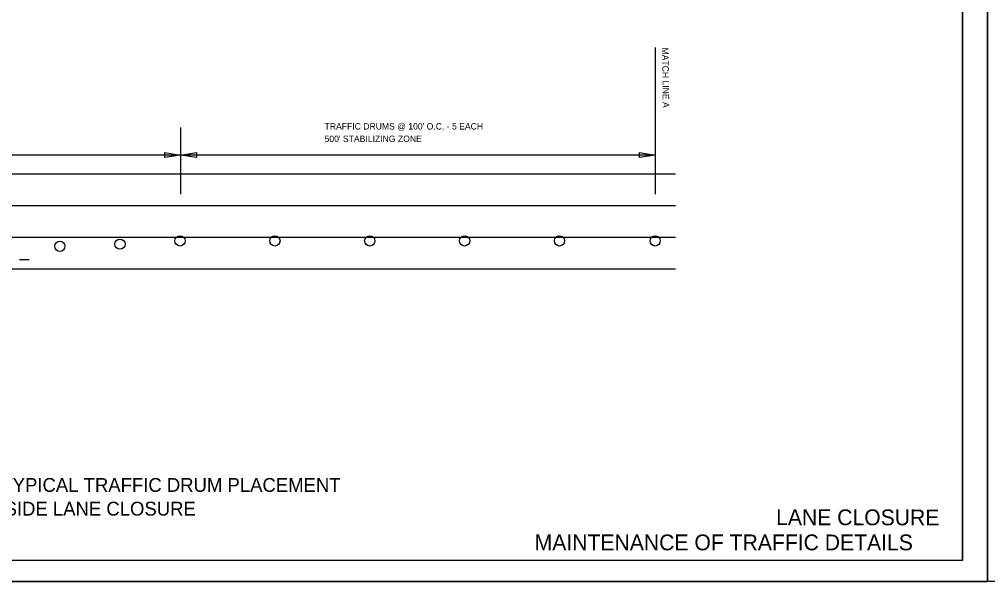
# Model space of a CAD drawing. Extents: x 1397271 to 1411271, y 376395 to 377888.
# Drawn here: x 1402985 to 1404271, y 376395 to 377141 of the extents above; entities that cross this region are included whole.
import ezdxf

# ---------------------------------------------------------------- set-up
doc = ezdxf.new("R2010")
doc.units = 0
for name, color, linetype in [('Default', 7, 'Continuous'), ('R_Border', 7, 'Continuous'), ('R_MOT', 7, 'Continuous'), ('R_No Plot', 7, 'Continuous')]:
    doc.layers.add(name, color=color, linetype=linetype)

msp = doc.modelspace()

# ---------------------------------------------------------------- linework, layer by layer
at = {"layer": 'Default'}
for p, q in [((1403829.7, 377103.9), (1403829.7, 376909.1)), ((1403199.1, 376997.5), (1403199.1, 376909.1)), ((1403178.1, 376958), (1403178.1, 376964.3)), ((1403178.1, 376964.3), (1403199.1, 376961.1)), ((1403199.1, 376961.1), (1403220.2, 376964.3)), ((1403220.2, 376964.3), (1403220.2, 376958)), ((1403808.6, 376958), (1403808.6, 376964.3)), ((1403808.6, 376964.3), (1403829.7, 376961.1)), ((1403257.1, 376961.1), (1402241.4, 376961.1)), ((1403199.1, 376961.1), (1403178.1, 376958)), ((1403829.7, 376961.1), (1403199.1, 376961.1)), ((1403220.2, 376958), (1403199.1, 376961.1)), ((1403829.7, 376961.1), (1403808.6, 376958)), ((1402218.9, 376936), (1403856.5, 376936)), ((1402218.9, 376893.9), (1403856.5, 376893.9)), ((1402218.9, 376851.9), (1403856.5, 376851.9)), ((1402218.9, 376809.9), (1403856.5, 376809.9))]:
    msp.add_line(p, q, dxfattribs=at)
at = {"layer": 'R_Border'}
for q in [(1404237.9, 377860.7), (1402024.6, 376422.5)]:
    msp.add_line((1404237.9, 376422.5), q, dxfattribs=at)
at = {"layer": 'R_MOT'}
msp.add_line((1402985.2, 376822.4), (1402998.1, 376822.4), dxfattribs=at)
for centre in [(1403038.9, 376839.9), (1403118.7, 376842.7), (1403198.5, 376847.1), (1403324.5, 376847.1), (1403450.5, 376847.1), (1403576.5, 376847.1), (1403702.5, 376847.1), (1403829.6, 376847.1)]:
    msp.add_circle(centre, 6.8, dxfattribs=at)
at = {"layer": 'R_No Plot'}
msp.add_line((1401937.8, 376394.6), (1404271.1, 376394.6), dxfattribs=at)
for points in [[(1401937.7, 377888), (1404271.1, 377888), (1404271.1, 376394.6), (1401937.7, 376394.6)], [(1404271.1, 377888), (1406604.6, 377888), (1406604.6, 376394.6), (1404271.1, 376394.6)], [(1403662, 377860.7), (1403662, 377791.6), (1403912.2, 377791.6), (1403912.2, 377771.1), (1404074.6, 377771.1), (1404074.6, 377600.8), (1404237.9, 377600.8), (1404237.9, 376422.5), (1402024.6, 376422.5), (1402024.6, 377860.7)]]:
    msp.add_lwpolyline(points, close=True, dxfattribs=at)

# ---------------------------------------------------------------- texts
at = {"layer": 'Default'}
for s, height, rotation, p in [('MATCH LINE A', 8.54, 270.8059, (1403838.7, 377103.8)), ('LANE CLOSURE', 21, 359.9326, (1403990.2, 376469.6))]:
    msp.add_text(s, height=height, rotation=rotation, dxfattribs=at).set_placement(p)
for s, height, p in [("TRAFFIC DRUMS @ 100' O.C. - 5 EACH", 8.54, (1403390.5, 376995)), ("500' STABILIZING ZONE", 8.54, (1403390.5, 376978.4)), ('ADVANCE WARNING SIGNS & TYPICAL TRAFFIC DRUM PLACEMENT', 18.375, (1402603.5, 376513.8)), ('FOR OUTSIDE LANE CLOSURE', 18.375, (1402854.9, 376482.3))]:
    msp.add_text(s, height=height, dxfattribs=at).set_placement(p)
at = {"layer": 'R_Border'}
msp.add_text('MAINTENANCE OF TRAFFIC DETAILS', height=21, rotation=360, dxfattribs=at).set_placement((1403669.5, 376436.2))

doc.saveas('drawing.dxf')
